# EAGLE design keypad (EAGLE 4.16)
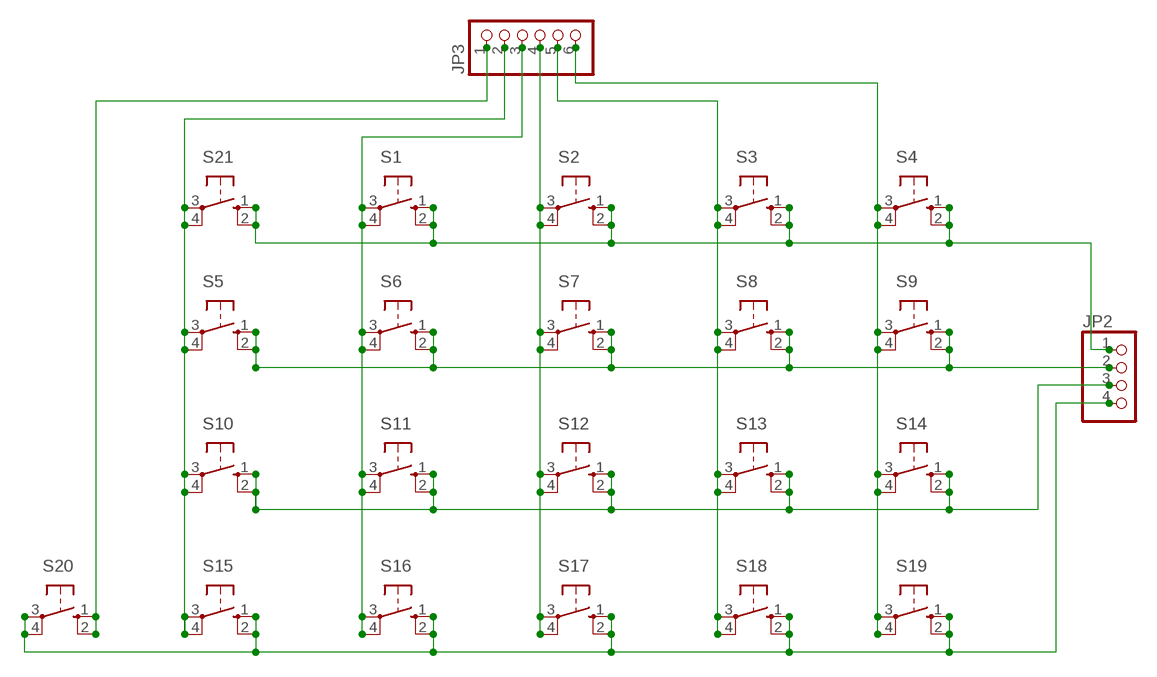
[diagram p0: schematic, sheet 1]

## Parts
JP2  PINHD-1X4  [1X04]
JP3  PINHD-1X6  [1X06]
S1  10-XX  [B3F-10XX]
S2  10-XX  [B3F-10XX]
S3  10-XX  [B3F-10XX]
S4  10-XX  [B3F-10XX]
S5  10-XX  [B3F-10XX]
S6  10-XX  [B3F-10XX]
S7  10-XX  [B3F-10XX]
S8  10-XX  [B3F-10XX]
S9  10-XX  [B3F-10XX]
S10  10-XX  [B3F-10XX]
S11  10-XX  [B3F-10XX]
S12  10-XX  [B3F-10XX]
S13  10-XX  [B3F-10XX]
S14  10-XX  [B3F-10XX]
S15  10-XX  [B3F-10XX]
S16  10-XX  [B3F-10XX]
S17  10-XX  [B3F-10XX]
S18  10-XX  [B3F-10XX]
S19  10-XX  [B3F-10XX]
S20  10-XX  [B3F-10XX]
S21  10-XX  [B3F-10XX]

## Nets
N$1: JP3.2 S5.3(P) S5.4(P1) S10.3(P) S10.4(P1) S15.3(P) S15.4(P1) S21.3(P) S21.4(P1)
N$3: JP3.6 S4.3(P) S4.4(P1) S9.3(P) S9.4(P1) S14.3(P) S14.4(P1) S19.3(P) S19.4(P1)
N$6: JP2.4 S15.1(S) S15.2(S1) S16.1(S) S16.2(S1) S17.1(S) S17.2(S1) S18.1(S) S18.2(S1) S19.1(S) S19.2(S1) S20.3(P) S20.4(P1)
N$13: JP3.1 S20.1(S) S20.2(S1)
N$21: JP3.3 S1.3(P) S1.4(P1) S6.3(P) S6.4(P1) S11.3(P) S11.4(P1) S16.3(P) S16.4(P1)
N$22: JP2.1 S1.1(S) S1.2(S1) S2.1(S) S2.2(S1) S3.1(S) S3.2(S1) S4.1(S) S4.2(S1) S21.1(S) S21.2(S1)
N$23: JP2.2 S5.1(S) S5.2(S1) S6.1(S) S6.2(S1) S7.1(S) S7.2(S1) S8.1(S) S8.2(S1) S9.1(S) S9.2(S1)
N$24: JP2.3 S10.1(S) S10.2(S1) S11.1(S) S11.2(S1) S12.1(S) S12.2(S1) S13.1(S) S13.2(S1) S14.1(S) S14.2(S1)
N$37: JP3.4 S2.3(P) S2.4(P1) S7.3(P) S7.4(P1) S12.3(P) S12.4(P1) S17.3(P) S17.4(P1)
N$60: JP3.5 S3.3(P) S3.4(P1) S8.3(P) S8.4(P1) S13.3(P) S13.4(P1) S18.3(P) S18.4(P1)

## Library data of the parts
JP2 = pinhead:PINHD-1X4: PIN HEADER
JP3 = pinhead:PINHD-1X6: PIN HEADER
S1-S21 = switch-omron:10-XX: OMRON SWITCH

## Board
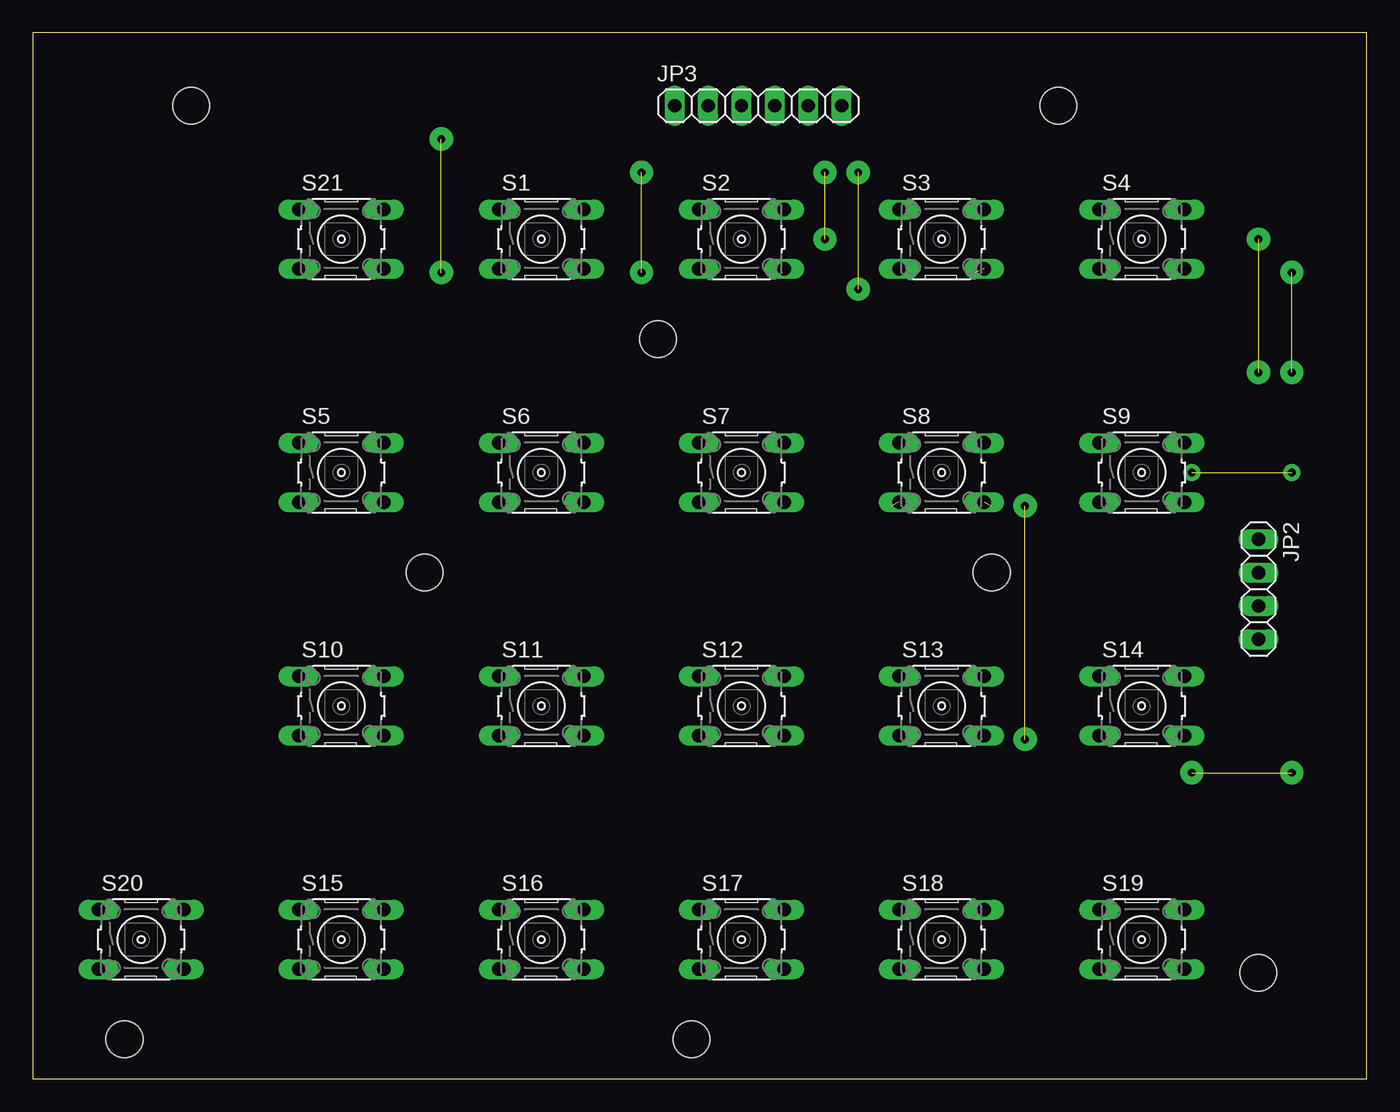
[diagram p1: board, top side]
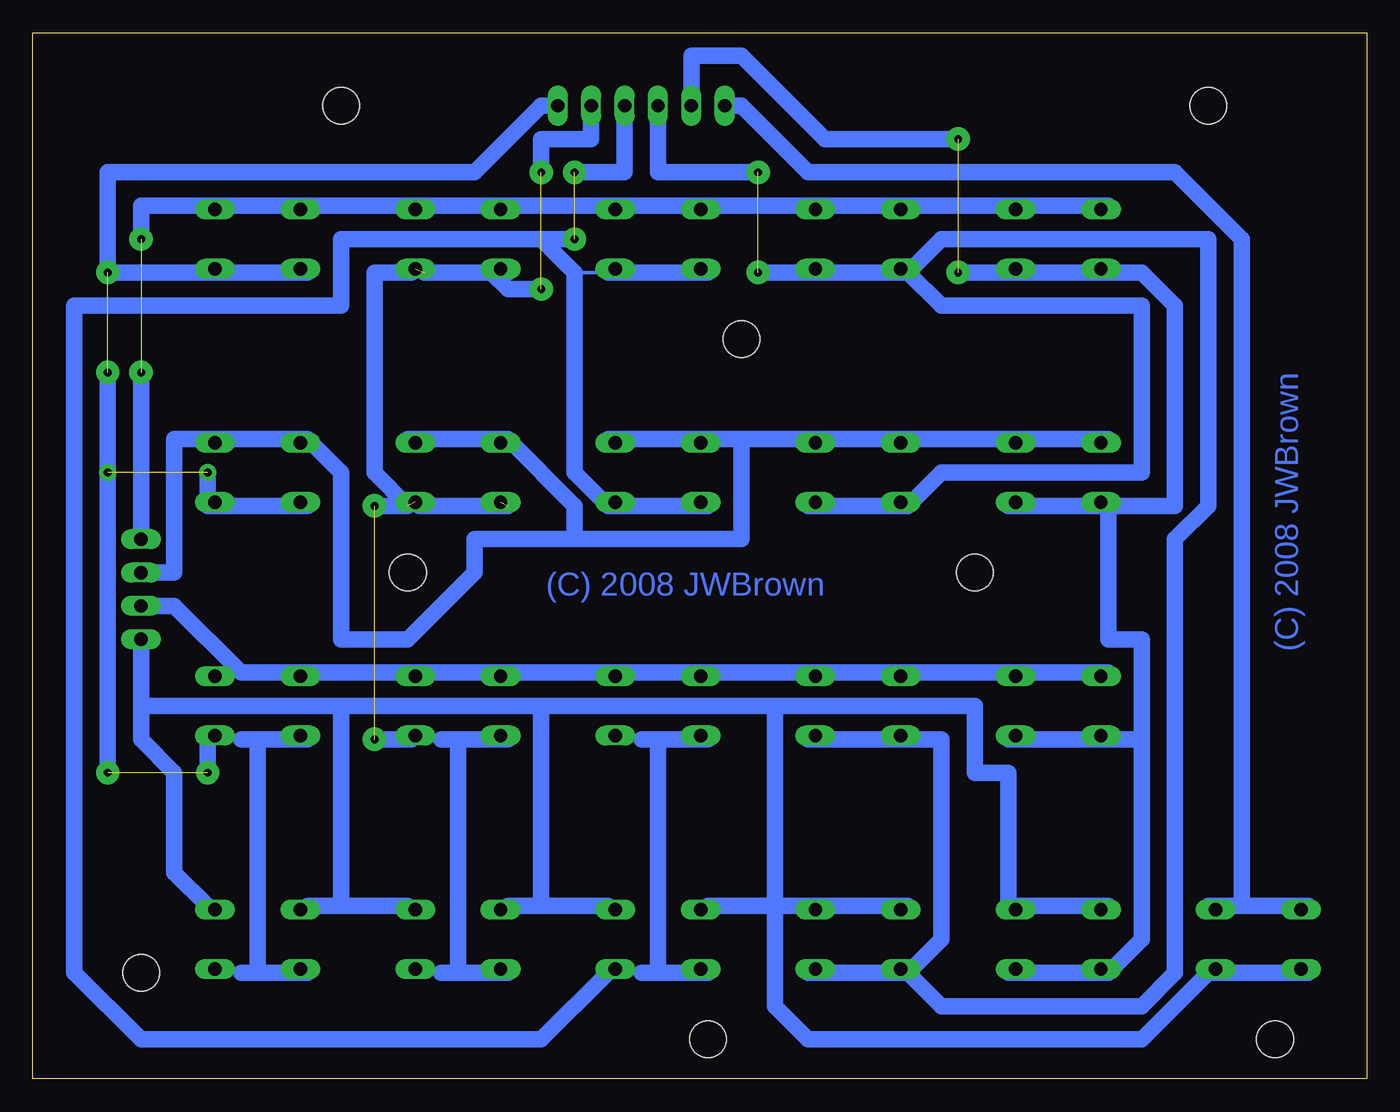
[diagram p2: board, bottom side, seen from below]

Size 101.58 x 79.68 mm. Coordinates in mm from the lower left corner, seen from the top.
Outline: 0,0 101.58,0 101.58,79.68 0,79.68 0,0
Copper layers (1*16): Top 0.035mm / dielectric 1.5mm / Bottom 0.035mm
Design rules "default": minimum track width 10mil, minimum drill 24mil, track to track 8mil, track to pad 8mil, pad to pad 8mil, via to via 8mil, smd to smd 8mil, copper to edge 40mil, drill to drill 8mil, minimum pad ring 10mil, minimum via ring 8mil, stop-mask expansion 4mil, vias tented up to drill 0mil, thermal gap 10mil
Holes 2.8 mm at 6.98,3.01 93.34,8.09 78.1,74.13 47.62,56.35 50.16,3.01 29.84,38.57 73.02,38.57 12.06,74.13

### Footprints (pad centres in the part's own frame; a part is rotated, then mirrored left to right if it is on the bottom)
1X04 = drill 1.016 long: 1 -3.81,0; 2 -1.27,0; 3 1.27,0; 4 3.81,0
1X06 = drill 1.016 long: 1 -6.35,0; 2 -3.81,0; 3 -1.27,0; 4 1.27,0; 5 3.81,0; 6 6.35,0
B3F-10XX = drill 1.016 long: 1 -3.251,2.261; 2 3.251,2.261; 3 -3.251,-2.261; 4 3.251,-2.261

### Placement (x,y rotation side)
JP2  93.34,37.3 270 top
JP3  55.24,74.13 0 top
S1  38.73,63.97 0 top
S2  53.97,63.97 0 top
S3  69.21,63.97 0 top
S4  84.45,63.97 0 top
S5  23.49,46.19 0 top
S6  38.73,46.19 0 top
S7  53.97,46.19 0 top
S8  69.21,46.19 0 top
S9  84.45,46.19 0 top
S10  23.49,28.41 0 top
S11  38.73,28.41 0 top
S12  53.97,28.41 0 top
S13  69.21,28.41 0 top
S14  84.45,28.41 0 top
S15  23.49,10.63 0 top
S16  38.73,10.63 0 top
S17  53.97,10.63 0 top
S18  69.21,10.63 0 top
S19  84.45,10.63 0 top
S20  8.25,10.63 0 top
S21  23.49,63.97 0 top

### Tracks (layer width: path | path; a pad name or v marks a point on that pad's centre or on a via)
N$1  (1 unrouted)
  Bottom 0.254: 27.3,61.43 S21.4 | 27.3,43.65 S5.4 | 27.3,8.09 S15.4 | 27.3,25.87 S10.4 | S15.3 19.68,8.09 | 19.68,25.87 S10.3 | 19.68,61.43 S21.3 | 19.68,43.65 S5.3
  Bottom 1.27: 26.03,61.43 19.68,61.43 17.14,61.43 14.6,58.89 14.6,43.65 19.68,43.65 | 26.03,61.43 27.3,61.43 | 19.68,43.65 27.3,43.65 | 27.3,8.09 19.68,8.09 17.14,10.63 17.14,25.87 | 27.3,25.87 19.68,25.87 17.14,25.87 | 19.68,43.65 19.68,33.49 17.14,33.49 17.14,25.87 | JP3.2 51.43,77.94 47.62,77.94 41.27,71.59 31.11,71.59 | S21.4 26.46,61.43 26.03,61.43 | 26.03,61.43 31.11,61.43
N$2  (via drill 0.6 pad 1.78)  (1 unrouted)
  other vias: 31.11,71.59 31.11,61.43
N$3  (via drill 0.6 pad 1.27, 0.6 pad 1.78)  (4 unrouted)
  Bottom 0.254: 80.64,61.43 S4.3 | 88.26,61.43 S4.4 | 85.72,8.09 88.26,8.09 S19.4 | S19.3 80.64,8.09 | 85.72,25.87 88.26,25.87 S14.4 | 80.64,25.87 S14.3 | S9.3 80.64,43.65 | 88.26,43.65 S9.4
  Bottom 1.27: 80.64,61.43 88.26,61.43 v95.88,61.43 95.88,69.05 67.94,69.05 62.86,74.13 JP3.6 | 80.64,8.09 84.45,8.09 | 84.45,8.09 85.72,8.09 | 84.45,25.87 80.64,25.87 | 84.45,25.87 85.72,25.87 | 80.64,43.65 88.26,43.65 v88.26,46.19 | 84.45,8.09 84.45,25.87 | S14.4 88.26,25.59 v88.26,23.33 | v95.88,23.33 v95.88,46.19 v95.88,53.81
N$4  (via drill 0.6 pad 1.78)  (1 unrouted)
  other vias: 75.56,43.65 75.56,25.87
N$5  (via drill 0.6 pad 1.78)  (1 unrouted)
  other vias: 46.35,69.05 46.35,61.43
N$6
  Bottom 0.254: S20.3 4.44,8.09 | 34.92,13.17 S16.1 | 50.16,13.17 S17.1 | 42.54,13.17 S16.2 | 12.06,8.09 S20.4 | 73.02,13.17 S18.2 | 80.64,13.17 S19.1 | 57.78,13.17 S17.2 | 65.4,13.17 S18.1 | 19.68,13.17 S15.1 | 93.34,28.41 93.34,25.87 | 88.26,13.17 S19.2 | 27.3,13.17 S15.2
  Bottom 1.27: 4.44,8.09 12.06,8.09 17.14,3.01 42.54,3.01 45.08,5.55 45.08,13.17 | 34.92,13.17 42.54,13.17 45.08,13.17 | 45.08,13.17 50.16,13.17 | 78.1,13.17 80.64,13.17 | 78.1,13.17 73.02,13.17 | 62.86,13.17 65.4,13.17 | 62.86,13.17 57.78,13.17 | 19.68,13.17 27.3,13.17 27.3,23.33 29.84,23.33 29.84,28.41 45.08,28.41 | 78.1,28.41 93.34,28.41 JP2.4 93.34,25.87 90.8,23.33 90.8,15.71 88.26,13.17 | 62.86,28.41 78.1,28.41 | 45.08,28.41 62.86,28.41 | 62.86,28.41 62.86,13.17 | 78.1,28.41 78.1,13.17 | 45.08,13.17 45.08,28.41
N$8  (via drill 0.6 pad 1.78)  (1 unrouted)
  other vias: 60.32,69.05 60.32,63.97
N$13
  Bottom 0.254: S20.1 4.44,13.17 | 12.06,13.17 S20.2
  Bottom 1.27: 9.52,13.17 12.06,13.17 | 4.44,13.17 9.52,13.17 | 9.52,13.17 9.52,63.97 14.6,69.05 42.54,69.05 47.62,74.13 JP3.1
N$21  (1 unrouted)
  Bottom 0.254: 42.54,8.09 S16.4 | 42.54,25.87 S11.4 | 34.92,25.87 S11.3 | 42.54,43.65 S6.4 | 42.54,61.43 S1.4 | 34.92,43.65 S6.3 | 34.92,8.09 S16.3 | 34.92,61.43 S1.3
  Bottom 1.27: 34.92,8.09 42.54,8.09 | 42.54,25.87 34.92,25.87 32.38,25.87 32.38,10.63 34.92,8.09 | 42.54,43.65 34.92,43.65 32.38,46.19 17.14,46.19 17.14,58.89 32.38,58.89 34.92,61.43 | 34.92,61.43 42.54,61.43 46.35,61.43 | 34.92,8.09 32.38,5.55 17.14,5.55 14.6,8.09 14.6,41.11 12.06,43.65 12.06,63.97 32.38,63.97 34.92,61.43 | JP3.3 53.97,69.05 46.35,69.05
N$22  (via drill 0.6 pad 1.78)  (1 unrouted)
  Bottom 0.254: S21.1 19.68,66.51 | 27.3,66.51 S21.2 | 34.92,66.51 S1.1 | 42.54,66.51 S1.2 | 50.16,66.51 S2.1 | 57.78,66.51 S2.2 | 65.4,66.51 S3.1 | 73.02,66.51 S3.2 | 88.26,66.51 S4.2 | 80.64,66.51 S4.1
  Bottom 1.27: 19.68,66.51 27.3,66.51 34.92,66.51 42.54,66.51 50.16,66.51 57.78,66.51 65.4,66.51 73.02,66.51 80.64,66.51 88.26,66.51 93.34,66.51 v93.34,63.97 | v93.34,53.81 JP2.1
N$23
  Bottom 0.254: 88.26,48.73 S9.2 | 73.02,48.73 S8.2 | S5.1 19.68,48.73 | 27.3,48.73 S5.2 | 34.92,48.73 S6.1 | 42.54,48.73 S6.2 | 57.78,48.73 S7.2 | 50.16,48.73 S7.1 | 65.4,48.73 S8.1 | 80.64,48.73 S9.1
  Bottom 1.27: JP2.2 90.8,38.57 90.8,48.73 88.26,48.73 80.64,48.73 78.1,46.19 78.1,33.49 73.02,33.49 67.94,38.57 67.94,41.11 60.32,41.11 | 73.02,48.73 65.4,48.73 60.32,43.65 60.32,41.11 | 19.68,48.73 27.3,48.73 34.92,48.73 42.54,48.73 47.62,48.73 | 47.62,48.73 50.16,48.73 57.78,48.73 | 60.32,41.11 47.62,41.11 47.62,48.73
N$24
  Bottom 0.254: S10.1 19.68,30.95 | 27.3,30.95 S10.2 | 34.92,30.95 S11.1 | 42.54,30.95 S11.2 | 50.16,30.95 S12.1 | 57.78,30.95 S12.2 | 65.4,30.95 S13.1 | 73.02,30.95 S13.2 | 85.72,30.95 88.26,30.95 S14.2 | 80.64,30.95 S14.1
  Bottom 1.27: 19.68,30.95 27.3,30.95 34.92,30.95 42.54,30.95 50.16,30.95 57.78,30.95 65.4,30.95 73.02,30.95 80.64,30.95 85.72,30.95 90.8,36.03 JP2.3
N$37  (1 unrouted)
  Bottom 0.254: 55.24,8.09 57.78,8.09 S17.4 | S17.3 50.16,8.09 | 55.24,25.87 57.78,25.87 S12.4 | 50.16,25.87 S12.3 | 50.16,43.65 S7.3 | 50.16,61.43 S2.3 | 60.32,61.43 57.78,61.43 S2.4 | 57.78,43.65 S7.4
  Bottom 1.27: 50.16,8.09 53.97,8.09 | 53.97,8.09 55.24,8.09 | 53.97,25.87 50.16,25.87 | 53.97,25.87 55.24,25.87 | 50.16,43.65 57.78,43.65 60.32,46.19 60.32,61.43 62.86,63.97 | 57.78,61.43 50.16,61.43 | 57.78,8.09 62.86,3.01 93.34,3.01 98.42,8.09 98.42,58.89 78.1,58.89 78.1,63.97 62.86,63.97 | 62.86,63.97 60.32,63.97 | JP3.4 56.51,69.05 60.32,69.05 | 53.97,8.09 53.97,25.87
N$60  (via drill 0.6 pad 1.78)  (5 unrouted)
  Bottom 0.254: 70.48,8.09 73.02,8.09 S18.4 | S18.3 65.4,8.09 | 70.48,25.87 73.02,25.87 S13.4 | 65.4,25.87 S13.3
  Bottom 1.27: 65.4,8.09 69.21,8.09 | 69.21,8.09 70.48,8.09 | 69.21,25.87 65.4,25.87 | 69.21,25.87 70.48,25.87 | S3.3 66.24,61.43 66.67,61.43 | 66.67,61.43 71.75,61.43 | JP3.5 59.05,71.59 62.86,71.59 v62.86,69.05 | 69.21,8.09 69.21,25.87 | S8.4 72.18,43.65 65.4,43.65 | S3.4 72.74,61.43 75.56,61.43 75.56,46.19 73.02,43.65 75.56,43.65 | 66.67,61.43 65.4,61.43 | 66.67,61.43 65.4,60.16 v62.86,60.16 | S13.4 72.74,25.87 75.56,25.87

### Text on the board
Bottom: (C) 2008 JWBrown | (C) 2008 JWBrown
